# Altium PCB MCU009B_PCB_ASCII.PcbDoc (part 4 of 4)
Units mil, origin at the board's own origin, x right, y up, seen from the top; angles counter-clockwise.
Board outline 2657.23 x 2215.46 mil, 10 copper layers (Top Layer, Internal-Plane 2, Mid-Layer 3, Mid-Layer 4, Internal-Plane 5, Internal-Plane 6, Mid-Layer 7, Mid-Layer 8, Internal-Plane 9, Bottom Layer), stack 60.8 mil thick; 232 components, 196 nets, 851 pads, 493 vias.
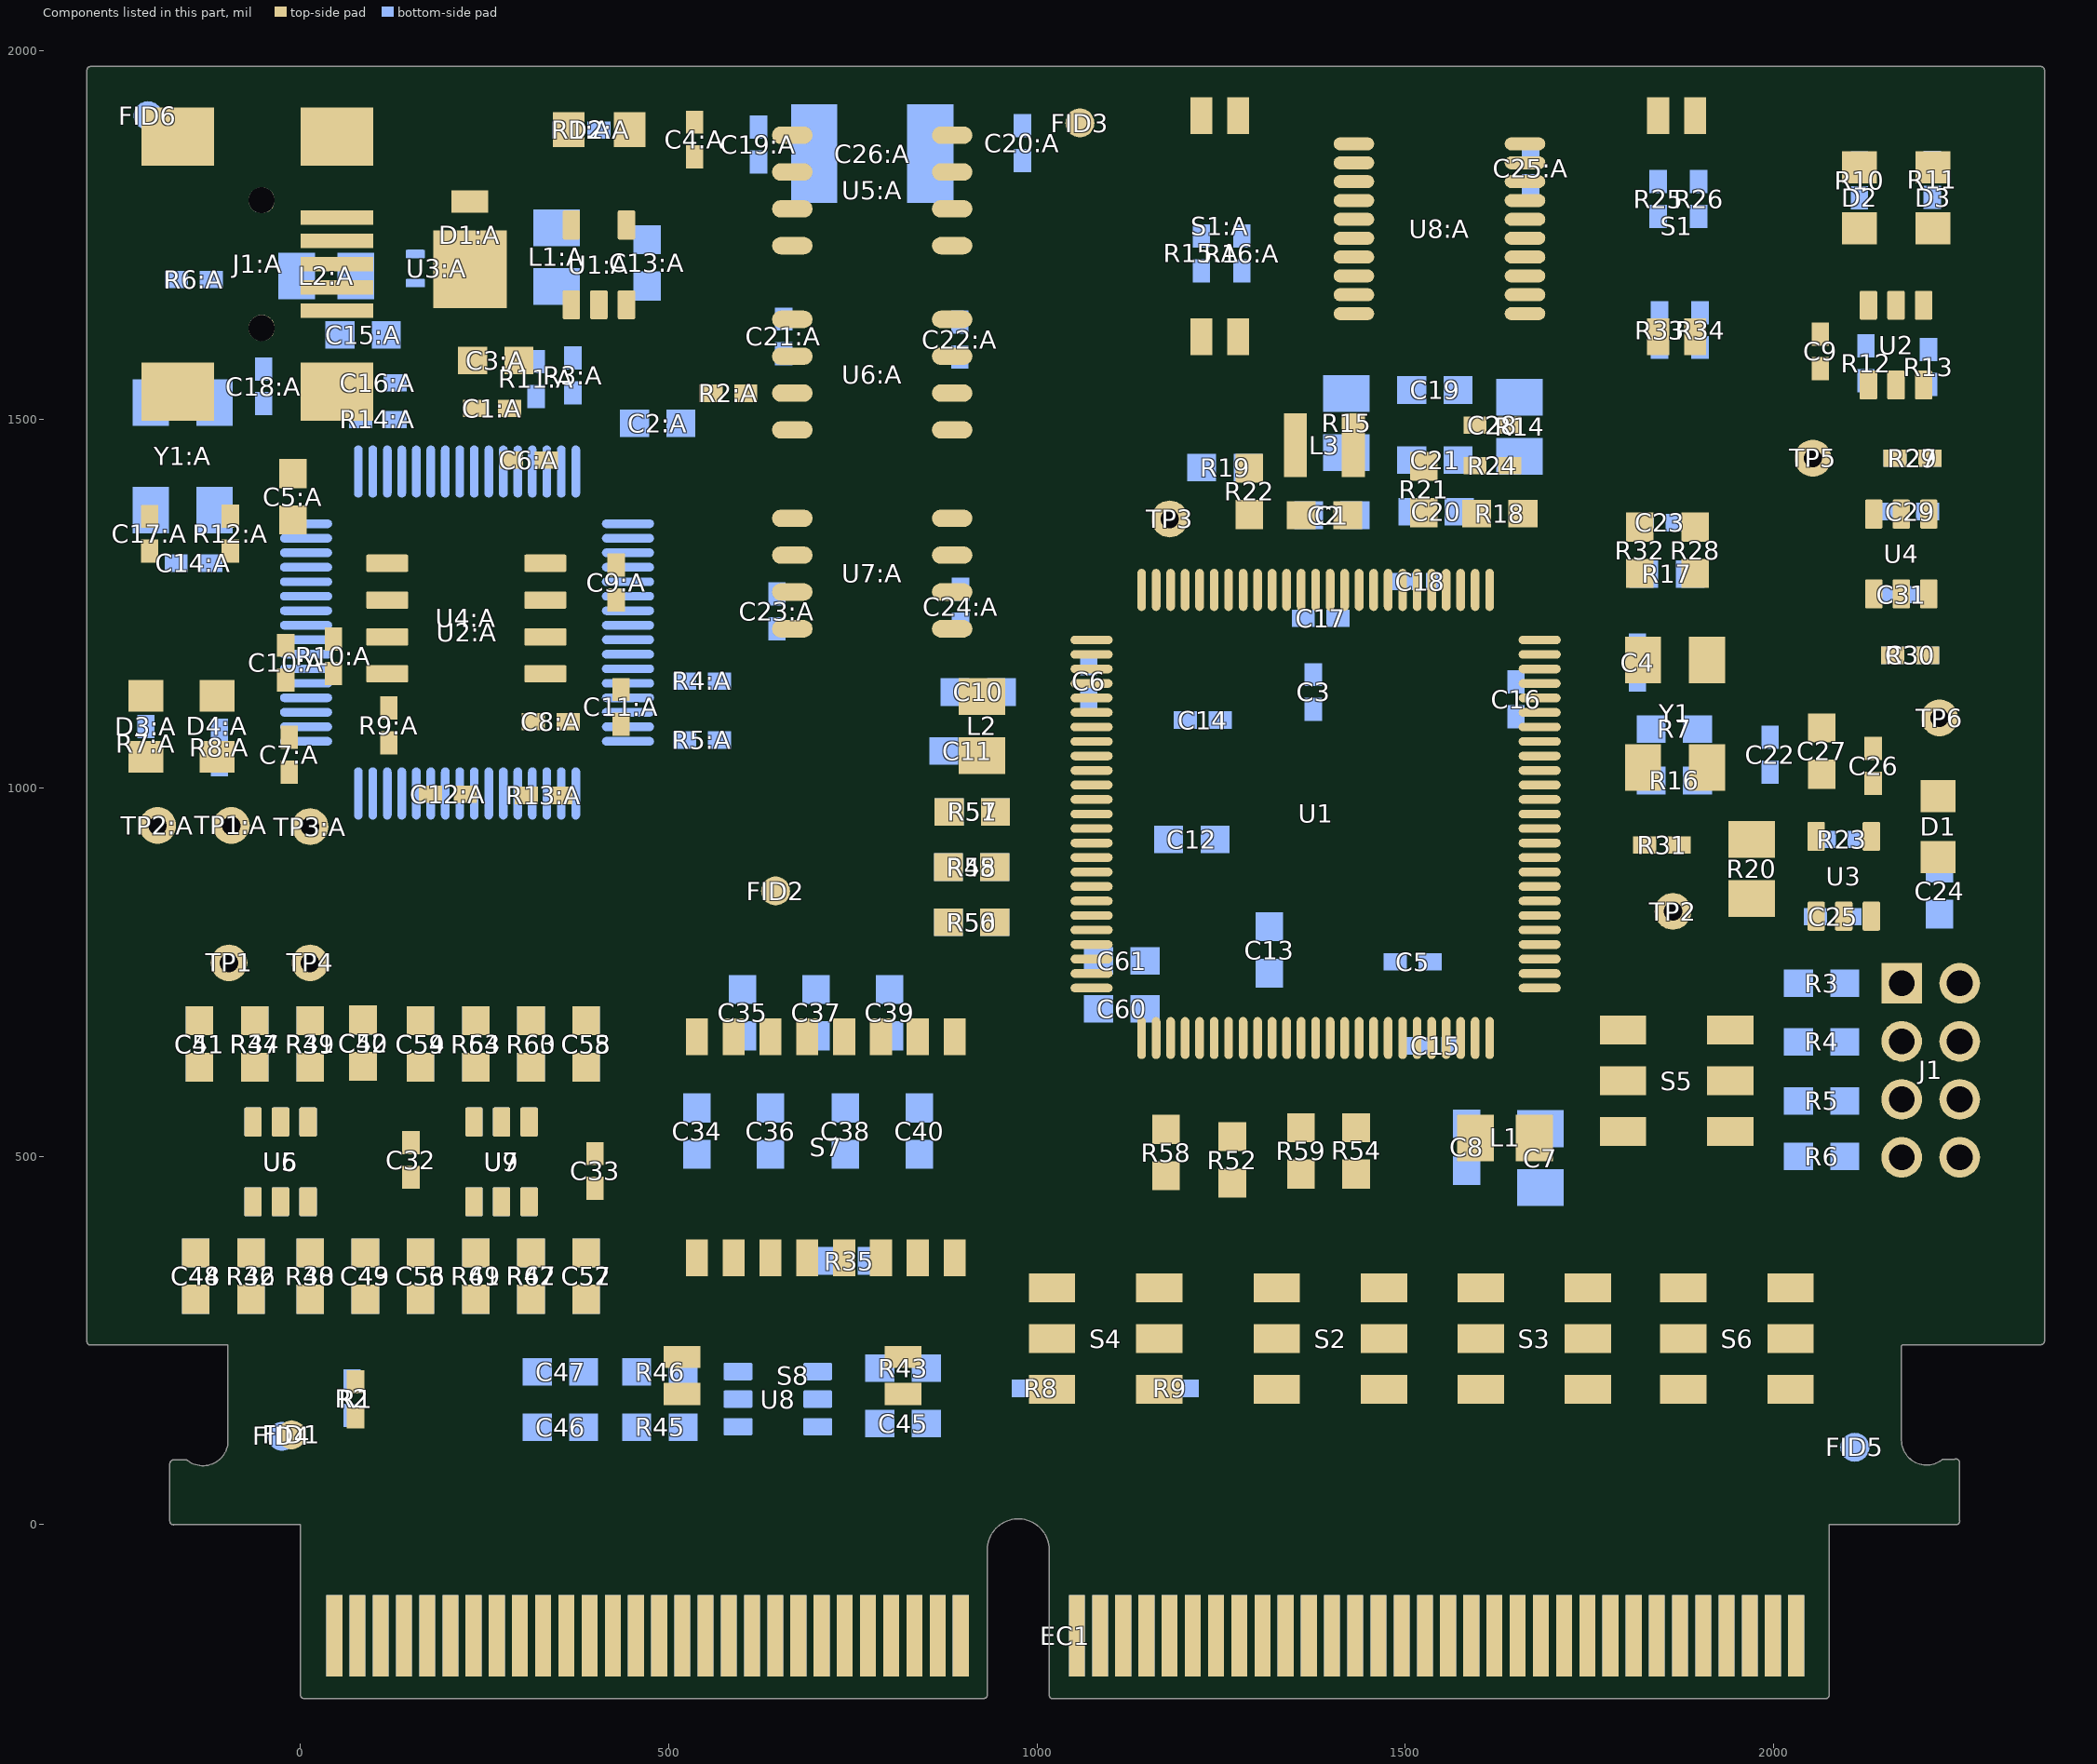
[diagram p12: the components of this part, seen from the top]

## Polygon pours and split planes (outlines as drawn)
GND on Mid-Layer 7 "Mid-Layer 7-No Net" (solid, pour order 6): -270,799 -270,264 -257,264 -99,264 cw(c-99,243) -78,243 -78,238 -78,113 cw(c-131,113) -131,60 -132,60 -136,60 -157,66 -157,20 -143,20 0,20 cw(c0,0) 20,0 20,-216 912,-216 912,-34 cw(c974,-34) 974,28 975,28 978,28 cw(c978,-31) 1037,-31 1037,-216 2055,-216 2055,-1 cw(c2076,-1) 2076,20 2232,20 2232,66 2218,61 2207,61 2204,61 cw(c2204,106.87) 2171.57,74.43 2164,82 cw(c2190.56,108.56) 2153,108.56 2153,122 2153,241 2153,242 cw(c2175,242) 2175,264 2347,264 2347,1959 2323,1959 827,1959 827,1123 827,1119 825,1117 793,1085 813,1085 985,1085 985,1127 985,1129 985,1128 1000,1141 1126,1141 1162,1105 1192,1105 1214,1083 1214,959 1232,941 1343,941 1365,919 1365,822 1402,785 1442,785 1510,717 1510,470 1432,392 995,392 946,343 946,220 781,55 777,55 774,58 774,62 936,224 936,347 991,402 1428,402 1500,474 1500,713 1438,775 1397,775 1355,818 1355,915 1339,931 1228,931 1204,955 1204,1079 1188,1095 1158,1095 1122,1131 1004,1131 995,1123 995,1075 990,1075 783,1075 507,799
EMU_GND on Internal-Plane 2 (split plane): 726,1160.07 464.77,898.84 -269.63,898.84 -269.63,1959.01 726,1959.01
GND on Internal-Plane 2 (split plane): 257 vertices, not listed, extent -269.63,-216.18 2347.33,1959.01
EMU_GND on Internal-Plane 5 (split plane): 725.99,1160.06 464.77,898.84 -269.63,898.84 -269.63,1959.01 725.99,1959.01
GND on Internal-Plane 5 (split plane): 235 vertices, not listed, extent -269.63,-216.18 2347.33,1959.01
MCU_1V2 on Internal-Plane 6 (split plane): 1706.9,1295.72 1706.9,1271 1707.29,1269.05 1708.4,1267.4 1764.9,1210.89 1764.9,1199.23 1764.9,1188 1765.29,1186.05 1766.4,1184.4 1768.05,1183.29 1769.86,1182.93 1779.4,1173.4 1781.05,1172.29 1781.61,1172.18 1804.9,1148.89 1804.9,1097.11 1748.89,1041.1 1735,1041.1 1733.05,1040.71 1731.4,1039.6 1686.4,994.6 1685.29,992.95 1684.9,991 1684.9,814.11 1661.4,790.6 1660.29,788.95 1659.9,787 1659.9,782 1659.9,695.1 1587.11,695.1 1555.1,727.11 1555.1,740 1555.1,765 1554.71,766.95 1553.6,768.6 1525.1,797.11 1525.1,870 1524.71,871.95 1523.6,873.6 1438.6,958.6 1436.95,959.71 1435,960.1 1432.11,960.1 1370.1,1022.11 1370.1,1157.89 1392.11,1179.9 1417.89,1179.9 1459.9,1137.89 1459.9,1122 1460.29,1120.05 1461.4,1118.4 1508.4,1071.4 1510.05,1070.29 1512,1069.9 1615,1069.9 1616.95,1070.29 1618.6,1071.4 1635.6,1088.4 1636.71,1090.05 1637.1,1092 1637.1,1138 1636.71,1139.95 1635.6,1141.6 1532.6,1244.6 1530.95,1245.71 1530.39,1245.82 1503.6,1272.6 1501.95,1273.71 1500,1274.1 1350,1274.1 1348.05,1273.71 1346.4,1272.6 1328.89,1255.1 1215,1255.1 1213.05,1254.71 1211.4,1253.6 1162.89,1205.1 1120,1205.1 1118.05,1204.71 1116.4,1203.6 1106.4,1193.6 1105.29,1191.95 1104.9,1190 1104.9,1141.1 995.1,1141.1 995.1,1231.16 995.1,1364.66 1045.34,1414.9 1587.72,1414.9
EMU_1V8 on Internal-Plane 6 (split plane): 329.38,1432.46 329.38,1369.12 314.09,1353.83 294.07,1353.83 279.57,1368.33 279.57,1386.09 279.18,1388.04 278.08,1389.69 276.42,1390.8 274.63,1391.15 266.95,1398.83 265.3,1399.94 263.35,1400.32 150.09,1400.32 148.14,1399.94 146.48,1398.83 136.15,1388.5 135.05,1386.84 134.66,1384.89 134.66,1153.21 135.05,1151.26 136.15,1149.61 172.31,1113.44 173.97,1112.34 175.92,1111.95 312.1,1111.95 365.15,1058.91 365.15,1030.94 336.34,1002.13 270.23,1002.13 239.43,1032.93 239.43,1068.57 239.05,1070.52 237.94,1072.17 215.69,1094.43 214.03,1095.53 212.08,1095.92 177.72,1095.92 175.77,1095.53 174.11,1094.43 119.18,1039.49 43.31,1039.49 7.36,1075.45 7.36,1290.31 6.97,1292.26 5.86,1293.92 -14.01,1313.79 -15.66,1314.89 -17.61,1315.28 -46.5,1315.28 -83.25,1352.03 -83.25,1388.74 -76.3,1395.69 -34.7,1395.69 -32.75,1396.08 -31.1,1397.18 13.51,1441.79 320.05,1441.79
MCU_3V3 on Internal-Plane 6 (split plane): 1524.4,1237.4 1526.05,1236.29 1526.61,1236.18 1626.9,1135.89 1626.9,1094.11 1612.89,1080.1 1514.11,1080.1 1470.1,1124.11 1470.1,1140 1469.71,1141.95 1468.6,1143.6 1423.6,1188.6 1421.95,1189.71 1420,1190.1 1390,1190.1 1388.05,1189.71 1386.4,1188.6 1361.4,1163.6 1360.29,1161.95 1359.9,1160 1359.9,1020 1360.29,1018.05 1361.4,1016.4 1426.4,951.4 1428.05,950.29 1430,949.9 1432.89,949.9 1514.9,867.89 1514.9,795 1515.29,793.05 1516.4,791.4 1544.9,762.89 1544.9,740 1544.9,725 1545.29,723.05 1546.4,721.4 1579.9,687.89 1579.9,665 1579.9,645 1579.9,635 1580.29,633.05 1581.4,631.4 1604.9,607.89 1604.9,580 1604.9,520.1 1510.1,520.1 1510.1,715 1509.71,716.95 1508.6,718.6 1443.6,783.6 1441.95,784.71 1440,785.1 1402.11,785.1 1365.1,822.11 1365.1,917 1364.71,918.95 1363.6,920.6 1344.6,939.6 1342.95,940.71 1341,941.1 1232.11,941.1 1214.1,959.11 1214.1,1081 1213.71,1082.95 1212.6,1084.6 1193.6,1103.6 1191.95,1104.71 1190,1105.1 1162.11,1105.1 1129.6,1137.6 1127.6,1139.6 1125.95,1140.71 1124,1141.1 1115.1,1141.1 1115.1,1187.89 1122.11,1194.9 1165,1194.9 1166.95,1195.29 1168.6,1196.4 1217.11,1244.9 1331,1244.9 1332.95,1245.29 1334.6,1246.4 1352.11,1263.9 1497.89,1263.9
MCU_A_3V3 on Internal-Plane 6 (split plane): 1122.4,1130.4 1156.4,1096.4 1158.05,1095.29 1160,1094.9 1187.89,1094.9 1203.9,1078.89 1203.9,957 1204.29,955.05 1205.4,953.4 1226.4,932.4 1228.05,931.29 1230,930.9 1338.89,930.9 1354.9,914.89 1354.9,820 1355.29,818.05 1356.4,816.4 1396.4,776.4 1398.05,775.29 1400,774.9 1437.89,774.9 1499.9,712.89 1499.9,227.11 1467.89,195.1 910,195.1 908.05,194.71 906.4,193.6 617.89,-94.9 238.11,-94.9 166.1,-22.89 166.1,309 165.71,310.95 164.6,312.6 93.6,383.6 91.95,384.71 90,385.1 -32.89,385.1 -49.9,402.11 -49.9,512.89 -27.89,534.9 0,534.9 1.95,535.29 3.6,536.4 13.6,546.4 14.71,548.05 15.1,550 15.1,667.89 92.11,744.9 540,744.9 541.95,745.29 543.6,746.4 872.11,1074.9 990,1074.9 991.95,1075.29 993.6,1076.4 994.71,1078.05 995.1,1080 995.1,1128.98 995.9,1130.9 1121.89,1130.9
3V3 on Internal-Plane 6 (split plane): 2347.33,895.1 2147.11,895.1 2128.6,913.6 2126.95,914.71 2125,915.1 2060,915.1 2058.05,914.71 2056.4,913.6 2016.4,873.6 2015.29,871.95 2014.9,870 2014.9,790 2015.29,788.05 2016.4,786.4 2054.9,747.89 2054.9,640 2054.9,202.11 1957.89,105.1 832.31,105.1 912.11,184.9 1470,184.9 1471.95,185.29 1473.6,186.4 1508.6,221.4 1509.71,223.05 1510.1,225 1510.1,509.9 1610,509.9 1611.95,510.29 1613.6,511.4 1614.71,513.05 1615.1,515 1615.1,580 1615.1,610 1614.71,611.95 1613.6,613.6 1590.1,637.11 1590.1,645 1590.1,684.9 1665,684.9 1666.95,685.29 1668.6,686.4 1669.71,688.05 1670.1,690 1670.1,782 1670.1,784.89 1693.6,808.4 1694.71,810.05 1695.1,812 1695.1,988.89 1737.11,1030.9 1751,1030.9 1752.95,1031.29 1754.6,1032.4 1813.6,1091.4 1814.71,1093.05 1815.1,1095 1815.1,1151 1814.71,1152.95 1813.6,1154.6 1787.6,1180.6 1785.95,1181.71 1785.39,1181.82 1775.6,1191.6 1775.1,1191.94 1775.1,1199.23 1775.1,1213 1774.71,1214.95 1773.6,1216.6 1717.1,1273.11 1717.1,1297.83 1716.71,1299.78 1715.6,1301.44 1593.44,1423.6 1591.78,1424.71 1589.83,1425.1 1043.23,1425.1 1041.27,1424.71 1039.62,1423.6 986.4,1370.38 985.29,1368.73 984.9,1366.77 984.9,1231.16 984.9,1130 984.9,1085.1 870,1085.1 868.05,1084.71 866.4,1083.6 537.89,755.1 90,755.1 88.05,754.71 86.4,753.6 6.4,673.6 5.29,671.95 4.9,670 4.9,552.11 -2.11,545.1 -30,545.1 -31.95,544.71 -33.6,543.6 -58.6,518.6 -59.71,516.95 -60.1,515 -60.1,400 -59.71,398.05 -58.6,396.4 -38.6,376.4 -36.95,375.29 -35,374.9 87.89,374.9 155.9,306.89 155.9,205.1 67.11,205.1 -61.4,333.6 -63.05,334.71 -65,335.1 -97.89,335.1 -149.9,387.11 -149.9,593.11 -121.26,626.53 -26.4,721.4 -25.29,723.05 -24.9,725 -24.9,798.84 506.2,798.84 825.99,1118.64 825.99,1959.01 2347.33,1959.01
EMU_3V3 on Internal-Plane 6 (split plane): 725.99,1160.06 464.77,898.84 -269.63,898.84 -269.63,1959.01 725.99,1959.01
HSEC_5V0 on Internal-Plane 6 (split plane): 187 vertices, not listed, extent -269.63,-216.18 2347.33,904.9
EMU_GND on Internal-Plane 9 (split plane): 726.08,1160.16 464.87,898.94 -269.63,898.94 -269.63,1959.01 726.08,1959.01
GND on Internal-Plane 9 (split plane): 233 vertices, not listed, extent -269.63,-216.18 2347.33,1959.01

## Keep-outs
Keep-Out Layer:
  text ".Layer_Name" at -3604.9,-2856.09 h60

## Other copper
Top Layer:
  text ".Layer_Name" at -3604.9,-2856.09 h60
Mid-Layer 3:
  text ".Layer_Name" at -3619,-2847 h60
Mid-Layer 4:
  text ".Layer_Name" at -3600,-2847 h60
Mid-Layer 7:
  text ".Layer_Name" at -3595,-2852 h60
Mid-Layer 8:
  text ".Layer_Name" at -3600,-2846 h60
Bottom Layer:
  text ".Layer_Name" at -3604.9,-2856.09 h60
Internal-Plane 2 (plane layer: these items are gaps in the copper):
  rectangle: -293.8,798.84 506.2,898.84
  rectangle: 726,1119 826,1977
  region: 506.19,798.84 825.99,1118.64 755.28,1189.35 435.48,869.55
  lines w10: 697.45,1007.09 697.45,1017.86 ; 776,1080 990,1080 990,1092.75 990,1118.25 990,1119.44 990,1125.81 1002.16,1136 1040,1136 1124,1136 1160,1100 1190,1100 1209,1081 1209,957 1230,936 1341,936 1360,917 1360,820 1400,780 1420,780 1440,780 1505,715 1505,472 1430,397 993,397 941,345 941,222 799,80 779,60 ; 776.47,1115.01 783.39,1121.93
  lines w40: -289.73,248.71 ccw(c-284.72,248.71) -284.72,243.7 -98.73,243.7 -98.73,238.74 ccw(c-93.71,238.74) -98.32,236.75 -98.32,115.84 -98.31,115.56 cw(c-132.26,113.93) -98.27,113.93 cw(c-132.26,113.93) -152.76,86.83 ccw(c-155.78,82.83) -155.78,87.84 -172.11,87.84 ccw(c-172.11,82.83) -175.66,86.37 -175.72,86.31 ccw(c-172.18,82.76) -177.19,82.76 -177.19,4.84 ccw(c-172.18,4.84) -171.01,-0.04 0.06,-0.04 0.06,-231.05 ccw(c5.07,-231.05) 5.9,-236 927.51,-236 ccw(c927.51,-230.98) 932.53,-230.98 ccw(c927.51,-230.98) 932.32,-229.56 932.32,-35.08 932.42,-34.1 cw(c974.4,-34.1) 1016.39,-34.1 1016.39,-231.27 ccw(c1021.4,-231.27) 1017.85,-234.81 1017.92,-234.88 ccw(c1021.47,-231.33) 1021.47,-236.35 1034.75,-236.35 1035.58,-236.28 2070.22,-236.28 ccw(c2070.22,-231.26) 2075.23,-231.26 2075.16,-230.44 2075.16,-0.11 2247.39,-0.11 ccw(c2247.39,4.91) 2252.41,4.91 ccw(c2247.39,4.91) 2252.2,6.33 2252.2,84.13 ccw(c2247.19,84.13) 2245.21,88.74 2230.93,88.74 ccw(c2230.93,83.73) 2227.9,87.73 cw(c2207.4,114.83) 2173.42,114.71 2173.42,242.73 2174.88,244.19 2362.35,244.19 ccw(c2362.35,249.21) 2365.9,245.66 2365.96,245.72 ccw(c2362.41,249.27) 2367.42,249.27 2367.42,1973.27 2367.49,1974.1 ccw(c2362.48,1974.1) 2362.48,1979.11 -284.69,1979.11 ccw(c-284.69,1974.1) -288.23,1977.64 -288.26,1977.62 ccw(c-284.72,1974.07) -289.73,1974.07 -289.73,248.71
  text ".Layer_Name" at -3619,-2838 h60
Internal-Plane 9 (plane layer: these items are gaps in the copper):
  region: 506.29,798.94 826.08,1118.73 755.37,1189.44 435.58,869.65
  rectangle: -293.71,798.94 506.29,898.94
  rectangle: 726.08,1118.73 826.08,1976.73
  lines w10: 760,1080 975,1080 990,1080 990,1125 1001,1136 1074,1136 1124,1136 1160,1100 1190,1100 1209,1081 1209,957 1230,936 1341,936 1360,917 1360,820 1400,780 1440,780 1505,715 1505,472 1430,397 993,397 941,345 941,222 779,60
  lines w40: -289.73,248.71 ccw(c-284.72,248.71) -284.72,243.7 -98.73,243.7 -98.73,238.74 ccw(c-93.71,238.74) -98.32,236.75 -98.32,115.84 -98.31,115.56 cw(c-132.26,113.93) -98.27,113.93 cw(c-132.26,113.93) -152.76,86.83 ccw(c-155.78,82.83) -155.78,87.84 -172.11,87.84 ccw(c-172.11,82.83) -175.66,86.37 -175.72,86.31 ccw(c-172.18,82.76) -177.19,82.76 -177.19,4.84 ccw(c-172.18,4.84) -171.01,-0.04 0.06,-0.04 0.06,-231.05 ccw(c5.07,-231.05) 5.9,-236 927.51,-236 ccw(c927.51,-230.98) 932.53,-230.98 ccw(c927.51,-230.98) 932.32,-229.56 932.32,-35.08 932.42,-34.1 cw(c974.4,-34.1) 1016.39,-34.1 1016.39,-231.27 ccw(c1021.4,-231.27) 1017.85,-234.81 1017.92,-234.88 ccw(c1021.47,-231.33) 1021.47,-236.35 1034.75,-236.35 1035.58,-236.28 2070.22,-236.28 ccw(c2070.22,-231.26) 2075.23,-231.26 2075.16,-230.44 2075.16,-0.11 2247.39,-0.11 ccw(c2247.39,4.91) 2252.41,4.91 ccw(c2247.39,4.91) 2252.2,6.33 2252.2,84.13 ccw(c2247.19,84.13) 2245.21,88.74 2230.93,88.74 ccw(c2230.93,83.73) 2227.9,87.73 cw(c2207.4,114.83) 2173.42,114.71 2173.42,242.73 2174.88,244.19 2362.35,244.19 ccw(c2362.35,249.21) 2365.9,245.66 2365.96,245.72 ccw(c2362.41,249.27) 2367.42,249.27 2367.42,1973.27 2367.49,1974.1 ccw(c2362.48,1974.1) 2362.48,1979.11 -284.69,1979.11 ccw(c-284.69,1974.1) -288.23,1977.64 -288.26,1977.62 ccw(c-284.72,1974.07) -289.73,1974.07 -289.73,248.71
  text ".Layer_Name" at -3603,-2855 h60
Internal-Plane 6 (plane layer: these items are gaps in the copper):
  rectangle: 725.99,1118.64 825.99,1976.64
  region: 506.19,798.84 825.99,1118.64 755.28,1189.35 435.48,869.55
  rectangle: -293.8,798.84 506.2,898.84
  lines w10: -30,800 -30,725 -125,630 -155,595 -155,385 -100,330 -91.25,330 -73.75,330 -65,330 65,200 160,200 ; 820,100 1960,100 2060,200 2060,640 2060,750 2020,790 2020,870 2060,910 2125,910 2145,890 2370,890 ; 1110,1136 1110,1190 1120,1200 1165,1200 1215,1250 1331,1250 1350,1269 1500,1269 1528,1241 1529,1241 1632,1138 1632,1092 1615,1075 1512,1075 1465,1122 1465,1140 1420,1185 1390,1185 1365,1160 1365,1020 1430,955 1435,955 1520,870 1520,795 1550,765 1550,740 1550,725 1585,690 ; 1505,515 1610,515 1610,580 1610,610 1585,635 ; 1585,645 1585,635 ; 1585,665 1585,690 ; 990,1130 990,1231.16 990,1366.77 1043.23,1420 1589.83,1420 1712,1297.83 1712,1271 1770,1213 1770,1199.23 1770,1188 1772,1188 1783,1177 1784,1177 1810,1151 1810,1095 1751,1036 1735,1036 1690,991 1690,812 1665,787 1665,782 1665,690 1585,690 ; 990,1130 990,1080 900,1080 870,1080 540,750 90,750 10,670 10,550 0,540 -30,540 -55,515 -55,400 -35,380 -10,380 90,380 161,309 161,-25 236,-100 620,-100 910,190 1470,190 1505,225 1505,715 1440,780 1400,780 1360,820 1360,917 1341,936 1230,936 1209,957 1209,1081 1190,1100 1160,1100 1126,1134 1124,1136 1027.5,1136 992.5,1136 990,1130 ; 1585,635 1585,690 ; -88.35,1349.92 -88.35,1390.85 -78.41,1400.79 -34.7,1400.79 11.4,1446.89 322.16,1446.89 334.48,1434.57 334.48,1367.01 316.2,1348.73 291.96,1348.73 274.47,1366.22 274.47,1386.09 272.49,1386.09 263.35,1395.23 150.09,1395.23 139.76,1384.89 139.76,1153.21 175.92,1117.05 314.21,1117.05 370.24,1061.02 370.24,1028.83 338.45,997.04 268.11,997.04 234.34,1030.81 234.34,1068.57 212.08,1090.82 177.72,1090.82 121.29,1034.39 41.2,1034.39 2.26,1073.34 2.26,1290.31 -17.61,1310.18 -48.61,1310.18 -88.35,1349.92
  lines w40: -289.73,248.71 ccw(c-284.72,248.71) -284.72,243.7 -98.73,243.7 -98.73,238.74 ccw(c-93.71,238.74) -98.32,236.75 -98.32,115.84 -98.31,115.56 cw(c-132.26,113.93) -98.27,113.93 cw(c-132.26,113.93) -152.76,86.83 ccw(c-155.78,82.83) -155.78,87.84 -172.11,87.84 ccw(c-172.11,82.83) -175.66,86.37 -175.72,86.31 ccw(c-172.18,82.76) -177.19,82.76 -177.19,4.84 ccw(c-172.18,4.84) -171.01,-0.04 0.06,-0.04 0.06,-231.05 ccw(c5.07,-231.05) 5.9,-236 927.51,-236 ccw(c927.51,-230.98) 932.53,-230.98 ccw(c927.51,-230.98) 932.32,-229.56 932.32,-35.08 932.42,-34.1 cw(c974.4,-34.1) 1016.39,-34.1 1016.39,-231.27 ccw(c1021.4,-231.27) 1017.85,-234.81 1017.92,-234.88 ccw(c1021.47,-231.33) 1021.47,-236.35 1034.75,-236.35 1035.58,-236.28 2070.22,-236.28 ccw(c2070.22,-231.26) 2075.23,-231.26 2075.16,-230.44 2075.16,-0.11 2247.39,-0.11 ccw(c2247.39,4.91) 2252.41,4.91 ccw(c2247.39,4.91) 2252.2,6.33 2252.2,84.13 ccw(c2247.19,84.13) 2245.21,88.74 2230.93,88.74 ccw(c2230.93,83.73) 2227.9,87.73 cw(c2207.4,114.83) 2173.42,114.71 2173.42,242.73 2174.88,244.19 2362.35,244.19 ccw(c2362.35,249.21) 2365.9,245.66 2365.96,245.72 ccw(c2362.41,249.27) 2367.42,249.27 2367.42,1973.27 2367.49,1974.1 ccw(c2362.48,1974.1) 2362.48,1979.11 -284.69,1979.11 ccw(c-284.69,1974.1) -288.23,1977.64 -288.26,1977.62 ccw(c-284.72,1974.07) -289.73,1974.07 -289.73,248.71
  text ".Layer_Name" at -3581,-2857 h60
Internal-Plane 5 (plane layer: these items are gaps in the copper):
  rectangle: 725.99,1118.64 825.99,1976.64
  region: 506.19,798.84 825.99,1118.64 755.28,1189.35 435.48,869.55
  rectangle: -293.8,798.84 506.2,898.84
  lines w10: 727,1080 990,1080 990,1126 1000,1136 1124,1136 1160,1100 1190,1100 1209,1081 1209,957 1230,936 1341,936 1360,917 1360,820 1400,780 1440,780 1505,715 1505,472 1430,397 1023,397 993,397 941,345 941,222 779,60
  lines w40: -289.73,248.71 ccw(c-284.72,248.71) -284.72,243.7 -98.73,243.7 -98.73,238.74 ccw(c-93.71,238.74) -98.32,236.75 -98.32,115.84 -98.31,115.56 cw(c-132.26,113.93) -98.27,113.93 cw(c-132.26,113.93) -152.76,86.83 ccw(c-155.78,82.83) -155.78,87.84 -172.11,87.84 ccw(c-172.11,82.83) -175.66,86.37 -175.72,86.31 ccw(c-172.18,82.76) -177.19,82.76 -177.19,4.84 ccw(c-172.18,4.84) -171.01,-0.04 0.06,-0.04 0.06,-231.05 ccw(c5.07,-231.05) 5.9,-236 927.51,-236 ccw(c927.51,-230.98) 932.53,-230.98 ccw(c927.51,-230.98) 932.32,-229.56 932.32,-35.08 932.42,-34.1 cw(c974.4,-34.1) 1016.39,-34.1 1016.39,-231.27 ccw(c1021.4,-231.27) 1017.85,-234.81 1017.92,-234.88 ccw(c1021.47,-231.33) 1021.47,-236.35 1034.75,-236.35 1035.58,-236.28 2070.22,-236.28 ccw(c2070.22,-231.26) 2075.23,-231.26 2075.16,-230.44 2075.16,-0.11 2247.39,-0.11 ccw(c2247.39,4.91) 2252.41,4.91 ccw(c2247.39,4.91) 2252.2,6.33 2252.2,84.13 ccw(c2247.19,84.13) 2245.21,88.74 2230.93,88.74 ccw(c2230.93,83.73) 2227.9,87.73 cw(c2207.4,114.83) 2173.42,114.71 2173.42,242.73 2174.88,244.19 2362.35,244.19 ccw(c2362.35,249.21) 2365.9,245.66 2365.96,245.72 ccw(c2362.41,249.27) 2367.42,249.27 2367.42,1973.27 2367.49,1974.1 ccw(c2362.48,1974.1) 2362.48,1979.11 -284.69,1979.11 ccw(c-284.69,1974.1) -288.23,1977.64 -288.26,1977.62 ccw(c-284.72,1974.07) -289.73,1974.07 -289.73,248.71
  text ".Layer_Name" at -3576,-2852 h60

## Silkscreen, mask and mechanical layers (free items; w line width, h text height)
Top Overlay:
  region: 2292.34,1969.69 2292.34,1825 2357,1825 2357,1969.69
  lines w4: -45,255 -25,275
  text "ON" at 1140.99,1898 h20
  text "1" at 1946,1898 h20
  text "-" at 2344,1763 h40 r90
  text "BOOT" at 1983,1724 h20 r90
  text ".PCB_Rev" at 2342,1691 h40 r90
  text "JTAG ISO" at 1152,1683 h20 r90
  text "UART ISO" at 1363,1683 h20 r90
  text "OFF" at 1121,1602 h20
  text "0" at 1941,1601 h20
  text "OutFilt" at 818,703 h20
  text "C2000 F28004x controlCARD" at 2346,665 h40 r90
  text "PGA" at 979,486 h20 r90
  text "cJTAG" at 1049,388 h20
  text "Thru" at 861.32,297 h20
  text "Int" at 479,119 h20
  text "Ext" at 809,119 h20
  text "VREFHI" at 576,93 h20
  text "Std JTAG" at 1025,75 h20
  text "1" at 46.06,6.81 h30
  text "57" at 1038.19,6.81 h30
  text "119" at 1955.51,6.81 h30
  text "55" at 870,-5 h30
  text ".Layer_Name" at -3604.9,-2856.09 h60
Bottom Overlay:
  text "TMDSCNCD280049C" at 1892,111 h40
  text "'.PCB_Rev'" at 1648,48 h40
  text ".PRJ_Number" at 1891,48 h40
  text "2" at 57.87,6.81 h30
  text "58" at 1089.37,6.81 h30
  text "120" at 2022.44,6.81 h30
  text "56" at 915,-5 h30
  text ".Layer_Name" at -3604.9,-2856.09 h60
Top Paste:
  text ".Layer_Name" at -3604.9,-2856.09 h60
Bottom Paste:
  text ".Layer_Name" at -3604.9,-2856.09 h60
Top Solder:
  text ".Layer_Name" at -3604.9,-2856.09 h60
  text ".Layer_Name" at -3604.9,-2856.09 h60
Bottom Solder:
  text ".Layer_Name" at -3604.9,-2856.09 h60
Drill Guide:
  text ".Layer_Name" at -3604.9,-2856.09 h60
M1 Board Outline:
  lines w4: -284.78,1474.65 -284.78,248.72 -284.76,248.7 -93.62,248.7 -93.75,248.57 -93.75,115.24 -93.68,115.18 ; -284.78,1947.09 -284.68,1947.19 -284.68,1973.99 -284.57,1974.1 2362.36,1974.1 2362.36,249.2 2168.79,249.2 2168.46,248.86 2168.46,116.77 ccw(c2207.41,114.86) 2230.94,83.76 2247.19,83.76 2247.24,83.8 2247.24,4.91 ; -93.34,115.83 cw(c-132.3,113.92) -155.82,82.82 -172.1,82.82 -172.14,82.78 -172.14,4.89 -172.08,4.95 5.05,4.95 5.11,4.89 5.11,-231.04 5.17,-230.98 927.3,-230.98 927.3,-34.43 ; 1022.44,-34.43 1022.44,-231.33 1022.51,-231.27 2070.19,-231.27 2070.19,4.83 2070.27,4.91 2247.24,4.91 ; 2247.24,4.91 2247.24,4.91
  text ".Layer_Name" at -3593,-2846 h60
M2 Board Dimensions:
  rectangle: -4056.9,-2397.6 -3681.9,-2272.6
  rectangle: -4181.9,-2272.6 -4056.9,-2147.6
  lines w7: -4181.9,-2272.6 -3181.9,-2272.6 ; -4056.9,-2397.6 -4056.9,-2147.6 ; -3931.9,-2397.6 -3931.9,-2147.6 ; -3681.9,-2397.6 -3681.9,-2147.6 ; -3431.9,-2397.6 -3431.9,-2147.6 ; -4181.9,-2397.6 -4181.9,-2147.6 -3181.9,-2147.6 -3181.9,-2397.6 -4181.9,-2397.6
  lines w10: -3200,-522 -3132,-522 ; -3158,-551 -3131,-523 ; -3158,-492 -3131,-522 ; -3124,823 -3056,905 ; -3122,-569 -3122,-247 ; -3122,-206 -3072,-260 -2962,-260 -2915,-203 ; -3122,-204 -3122,826 ; -3057,906 -2993,819 ; -3039,-354 -2971,-354 ; -2997,-383 -2970,-355 ; -2997,-324 -2970,-354 ; -2992,818 -2920,908 ; -2961,-569 -2961,-287 ; -2915,-204 -2915,826 -2915,911 ; -2914,-569 -2914,-247 ; -2908.04,446.62 cw(c-2964,-261) -2524.66,296.54 ; -2906.16,445.26 ccw(c-2766.4,679.92) -2855.29,421.66 ; -2906,-519 -2879,-549 ; -2906,-518 -2879,-490 ; -2906,452 cw(c-2873.55,278.02) -2843.28,452.39 ; -2904,-518 -2836,-518 ; -2904,-355 -2877,-385 ; -2904,-354 -2877,-326 ; -2902,-354 -2834,-354 ; -2888,-165 -2425,407 ; -2578,311 ccw(c-2440.48,651.43) -2523.34,293.74 ; -2560.75,344.3 cw(c-2677.61,210.86) -2522,296
  text "30" at -2719,467 h60
  text "18MIL" at -2793,-382 h60
  text "62MIL" at -2800,-546 h60
  text "GOLD FINGER" at -3281,-783 h60
  text "SIDE VIEW" at -3227,-896 h60
  text ".Layer_Name" at -3604.9,-2856.09 h60
M3 3D STEP Top:
  text ".Layer_Name" at -3604.9,-2856.09 h60
M4 3D STEP Bottom:
  text ".Layer_Name" at -3604.9,-2856.09 h60
M5 Assembly Top:
  lines w10: -4473.9,-2927.77 2126.1,-2927.77 ; -4473.9,-2724.43 2128.1,-2724.43 ; -4473.9,-2521.1 -4473.9,-3131.1 -468.9,-3131.1 2128.1,-3131.1 2128.1,-2521.1 -4473.4,-2521.1 -4473.4,-3131.1 -2897.9,-3131.1 ; -2008.9,-3131.1 -2008.9,-2521.1 ; -741.9,-2724.43 -741.9,-2521.1 ; 98.1,-2724.43 98.1,-2521.1 ; 720.1,-3137.6 720.1,-2934.77
  text "COMPONENTS MARKED 'DNP' SHOULD NOT BE POPULATED." at -3028.4,-2316.1 h60
  text "ASSEMBLY VARIANT:" at -3028.9,-2431.6 h60
  text ".VariantName" at -1992.9,-2431.6 h60
  text "PCB VIEWED FROM TOP SIDE" at -4410.4,-2653.27 h60
  text "BOARD #:" at -1933.9,-2653.27 h60
  text ".PRJ_Number" at -1388.4,-2653.27 h60
  text "REV:" at -543.9,-2653.27 h60
  text ".PCB_Rev" at -252.4,-2653.27 h60
  text "SVN REV:" at 294.1,-2653.27 h60
  text ".VersionControl_RevNumber" at 800.1,-2653.27 h60
  text "TID #:" at -1933.9,-2856.6 h60
  text ".TID" at -1388.4,-2856.6 h60
  text "PLOT NAME =" at -4410.4,-3061.94 h60
  text ".plot_File_Name" at -3604.9,-3061.94 h60
  text "GENERATED    :" at -1931.9,-3061.94 h60
  text ".Print_Date" at -1062.4,-3061.94 h60
  text ".Print_Time" at -333.4,-3061.94 h60
  text "TEXAS INSTRUMENTS" at 931.1,-3061.94 h60
M6 Assembly Bottom:
  lines w10: -4474.4,-2724.93 2127.6,-2724.93 ; -4472.4,-2928.27 2127.6,-2928.27 ; -3066.4,-3138.1 -3066.4,-2935.27 ; -2444.4,-2724.93 -2444.4,-2521.6 ; -1604.4,-2724.93 -1604.4,-2521.6 ; -337.4,-3131.6 -337.4,-2521.6 ; 551.6,-3131.6 2127.1,-3131.6 2127.1,-2521.6 -4474.4,-2521.6 -4474.4,-3131.6 -1877.4,-3131.6 2127.6,-3131.6 2127.6,-2521.6
  text "COMPONENTS MARKED 'DNP' SHOULD NOT BE POPULATED." at 1920.1,-2315.6 h60
  text ".VariantName" at 876.1,-2431.6 h60
  text "ASSEMBLY VARIANT:" at 1915.1,-2431.6 h60
  text ".VersionControl_RevNumber" at -3146.4,-2653.77 h60
  text "SVN REV:" at -2640.4,-2653.77 h60
  text ".PCB_Rev" at -2093.9,-2653.77 h60
  text "REV:" at -1802.4,-2653.77 h60
  text ".PRJ_Number" at -957.9,-2653.77 h60
  text "BOARD #:" at -412.4,-2653.77 h60
  text "PCB VIEWED FROM BOTTOM SIDE" at 2064.1,-2653.77 h60
  text ".TID" at -957.9,-2857.1 h60
  text "TID #:" at -412.4,-2857.1 h60
  text "TEXAS INSTRUMENTS" at -3277.4,-3062.44 h60
  text ".Print_Time" at -2012.9,-3062.44 h60
  text ".Print_Date" at -1283.9,-3062.44 h60
  text "GENERATED    :" at -414.4,-3062.44 h60
  text ".plot_File_Name" at 1258.6,-3062.44 h60
  text "PLOT NAME =" at 2064.1,-3062.44 h60
M9 Title Sheet:
  lines w10: -4673.4,-956.1 -4473.4,-956.1 ; -4673.4,1418.9 -4473.4,1418.9 ; -4673.4,3793.9 -4473.4,3793.9 ; -4473.4,-3133.1 -4473.4,5966.9 ; -4473.4,-3131.1 10126.6,-3131.1 ; -4473.4,5968.9 10126.6,5968.9 10126.6,-3131.1 ; -2173.4,-3331.1 -2173.4,-3131.1 ; -2173.4,5968.9 -2173.4,6168.9 ; 326.6,-3331.1 326.6,-3131.1 ; 326.6,5968.9 326.6,6168.9 ; 2139.1,-3131.1 2139.1,-2521.1 7121.6,-2521.1 ; 2826.6,-3331.1 2826.6,-3131.1 ; 2826.6,5968.9 2826.6,6168.9 ; 5326.6,-3331.1 5326.6,-3131.1 ; 5326.6,5968.9 5326.6,6168.9 ; 7121.6,-3131.1 7121.6,-2521.1 ; 7121.6,-2821.1 10121.6,-2821.1 ; 7121.6,-2221.1 10121.6,-2221.1 ; 7122.6,-1627.1 10122.6,-1627.1 ; 7826.6,-3331.1 7826.6,-3131.1 ; 7826.6,5968.9 7826.6,6168.9 ; 8626.6,-3121.1 8626.6,-2521.1 ; 10121.6,-2521.1 7121.6,-2521.1 ; 10121.6,-1921.1 7121.6,-1921.1 ; 10126.6,-1931.1 10126.6,-3131.1 ; 10126.6,-1126.6 7122.6,-1126.6 7121.6,-1126.6 7121.6,-1627.1 7121.6,-1921.1 ; 10126.6,-956.1 10326.6,-956.1 ; 10126.6,1418.9 10326.6,1418.9 ; 10126.6,3793.9 10326.6,3793.9 ; 7121.6,-2521.1 7121.6,-1921.1 ; -4673.4,-3331.1 10326.6,-3331.1 10326.6,6168.9 -4673.4,6168.9 -4673.4,-3331.1 ; -284.72,248.71 -93.71,248.71 -93.71,238.74 -93.3,238.33 -93.3,115.84 cw(c-132.26,113.93) -155.78,82.83 -172.11,82.83 -172.18,82.76 -172.18,69.68 -172.18,4.84 -172.04,4.98 4.59,4.98 5.07,4.5 5.07,-231.05 5.14,-230.98 20.63,-230.98 927.51,-230.98 927.3,-230.78 927.3,-34.2 927.4,-34.1 cw(c974.4,-34.1) 1021.4,-34.1 1021.4,-231.27 1021.47,-231.33 1034.75,-231.33 1034.82,-231.26 2070.22,-231.26 2070.15,-231.19 2070.15,4.77 2070.29,4.91 2247.39,4.91 2247.19,5.11 2247.19,84.13 2246.78,83.73 2230.93,83.73 cw(c2207.4,114.83) 2168.4,114.7 2168.4,244.8 2172.81,249.21 2362.35,249.21 2362.41,249.27 2362.41,1974.03 2362.48,1974.1 -284.69,1974.1 -284.72,1974.07 -284.72,248.71
  text "1" at -3442.06,6038.9 h70
  text "2" at -946.4,6038.9 h70
  text "3" at 1542.94,6038.9 h70
  text "4" at 4049.61,6038.9 h70
  text "5" at 6548.6,6038.9 h70
  text "6" at 9053.6,6038.9 h70
  text "A" at -4598.4,4895.9 h70
  text "A" at 10201.6,4895.9 h70
  text "B" at -4598.4,2515.9 h70
  text "B" at 10201.6,2515.9 h70
  text "C" at -4598.4,140.9 h70
  text "C" at 10201.6,140.9 h70
  text "PROJECT TITLE:" at 7161.6,-1720.1 h45
  text ".PRJ_Title" at 7211.6,-1853.43 h70
  text "DESIGNED FOR:" at 7161.6,-2021.1 h45
  text ".PRJ_Customer" at 7211.6,-2161.1 h70
  text "D" at -4598.4,-2229.1 h70
  text "D" at 10201.6,-2229.1 h70
  text "FILE NAME:" at 7161.6,-2321.1 h45
  text ".PCB_File_Name_No_Path" at 7211.6,-2441.1 h70
  text "Texas Instruments (TI) and/or its licensors do not warrant the accuracy or completeness of this specification" at 2192.1,-2602.94 h45
  text "ENGINEER:" at 7161.6,-2611.1 h45
  text "LAYOUT BY:" at 8666.6,-2611.1 h45
  text "or any information contained therein. TI and/or its licensors do not warrant that this design will meet" at 2147.11,-2715.6 h45
  text ".PRJ_Engineer" at 7211.6,-2766.09 h70
  text "QC Graphics Inc." at 8717.1,-2766.09 h70
  text "the specifications, will be suitable for your application or fit for any particular purpose, or will operate in" at 2147.11,-2828.27 h45
  text ".Layer_Name" at -3604.9,-2856.09 h60
  text "ALTIUM DESIGNER VERSION:" at 8666.6,-2921.1 h45
  text "an implementation. TI and/or its licensors do not warrant that the design is production worthy. You should" at 2147.11,-2940.93 h45
  text "completely validate and test your design implementation to confirm the system functionality for your application." at 2192.1,-3053.6 h45
  text ".print_Scale" at 7211.6,-3054.43 h70
  text ".Application_BuildNumber" at 8717.1,-3054.43 h70
  text "1" at -3442.06,-3261.1 h70
  text "2" at -946.4,-3261.1 h70
  text "3" at 1542.94,-3261.1 h70
  text "4" at 4049.61,-3261.1 h70
  text "5" at 6548.6,-3261.1 h70
  text "6" at 9053.6,-3261.1 h70
M10 Fab Notes:
  drawing of 173 lines, arcs and shapes, not listed
  text "DESIGN INFORMATION" at 8196.12,4203.4 h60
  text "MIN. TRACK WIDTH:" at 7551.56,4023.4 h60
  text "5" at 8647.8,4023.4 h60
  text "MIL" at 8802.56,4023.4 h60
  text "MIN. CLEARANCE:" at 7551.56,3891.4 h60
  text "0.1" at 8587.8,3891.4 h60
  text "mm" at 8802.56,3891.4 h60
  text "MIN. VIA PAD SIZE:" at 7551.56,3759.4 h60
  text "22" at 8617.81,3759.4 h60
  text "MIL" at 8802.56,3759.4 h60
  text "0.05mm (2MIL)" at 8246.56,3617.69 h60
  text "MINIMUM ANNULAR RING" at 7222.33,3613.4 h60
  text "EXTERNAL" at 8954.56,3613.4 h60
  text "PER" at 7422.33,3495.4 h60
  text "IPC-D-275 CLASS 2 LEVEL C" at 7642.33,3495.4 h60
  text "MIL, HOLES" at 9130.56,3383.11 h60
  text "+/-" at 8738.1,3382.4 h60
  text "+/-" at 9592.1,3382.4 h60
  text "REGISTRATION TOLERANCES:" at 7222.33,3377.4 h60
  text "METAL" at 8422.1,3377.4 h60
  text "5" at 8998.3,3377.4 h60
  text "3" at 9831.3,3377.4 h60
  text "MIL" at 9947.56,3377.4 h60
  text "+/-" at 9592.1,3264.4 h60
  text "HOLE SIZE TOLERANCE (UNLESS OTHERWISE SPECIFIED):" at 7222.33,3259.4 h60
  text "3" at 9831.3,3259.4 h60
  text "MIL" at 9947.56,3259.4 h60
  text "MATERIAL:" at 7147.56,3049.94 h60
  text "FR-4 High Tg" at 8134,2909.61 h60
  text "FR-408" at 7568.56,2901.04 h60
  text "OTHER" at 9056.56,2901.04 h60
  text "X" at 7979.1,2897.4 h60
  text "THICKNESS:" at 7222.33,2734.04 h60
  text "X" at 7760.5,2734.04 h60
  text "OTHER" at 9243.6,2734.47 h60
  text "62 MIL (1.6mm) +/- 6MIL" at 7896.21,2732.66 h60
  text "TOLERANCE:" at 7222.33,2576.04 h60
  text "X" at 8061.63,2576.04 h60
  text "ANSI IPC-6012 TYPE 3 CLASS 2" at 8248.58,2576.04 h60
  text "OTHER +/-" at 8248.56,2420.04 h60
  text "BOW & TWIST:" at 7222.33,2263.04 h60
  text "X" at 8061.63,2263.04 h60
  text "ANSI IPC-6012 TYPE 3 CLASS 2" at 8248.58,2263.04 h60
  text "OTHER +/-" at 8248.56,2104.53 h60
  text "DRILLING:" at 7147.56,1966.04 h60
  text "REFERENCE:" at 7222.33,1849.04 h60
  text "X" at 7870.56,1849.04 h60
  text "AS SHOWN" at 8057.56,1849.04 h60
  text "X" at 8771.56,1849.04 h60
  text "NC_DRILL FILES" at 8908.56,1849.04 h60
  text "PTH COPPER THICKNESS:" at 7222.33,1691.04 h60
  text "X" at 8352.56,1691.04 h60
  text "20-30 um" at 8489.56,1691.04 h60
  text "OTHER" at 9206.56,1691.04 h60
  text "BOARD FINISH:" at 7147.56,1532.04 h60
  text "SILKSCREEN:" at 7302.78,1414.04 h60
  text "X" at 8251.56,1414.04 h60
  text "TOP" at 8377.56,1414.04 h60
  text "X" at 8761.56,1414.04 h60
  text "BOTTOM" at 8888.56,1414.04 h60
  text "SILKSCREEN COLOR:" at 7302.78,1247.04 h60
  text "X" at 8250.52,1247.04 h60
  text "WHITE" at 8377.56,1247.04 h60
  text "OTHER" at 8888.56,1247.04 h60
  text "X" at 8381.52,1087.84 h60
  text "GREEN" at 8508.56,1087.84 h60
  text "OTHER" at 9126.56,1087.84 h60
  text "SOLDER RESIST COLOR:" at 7302.78,1077.04 h60
  text "X" at 8381.52,917.84 h60
  text "MATTE" at 8508.56,917.84 h60
  text "SEMI-GLOSS" at 9126.1,917.2 h60
  text "IMMERSION GOLD (ENIG)" at 8208.56,729.32 h60
  text "ENEPIG" at 9546.1,726.04 h60
  text "SURFACE FINISH:" at 7147.56,725.04 h60
  text "X" at 8021.61,725.04 h60
  text "HARD GOLD FINGERS" at 9228,570 h60
  text "IMM. TIN/SILVER OR EQUIV" at 7477.1,568.04 h60
  text "OTHER" at 8908.56,568.04 h60
  text "X" at 8715.61,552.04 h60
  text "ARRAY/PANEL:" at 7147.56,389.04 h60
  text "CUT AND TRIM PER M1 BOARD OUTLINE" at 8208.56,384.75 h60
  text "N.C. ROUTE" at 8208.56,233.04 h60
  text "X" at 8887.56,233.04 h60
  text "V. SCORE" at 9074.56,233.04 h60
  text "CERTIFICATION:" at 7147.56,96.04 h60
  text "MATERIALS AND WORKMANSHIP FOR ALL PCBS" at 7872.56,96.04 h60
  text "TO MEET OR EXCEED THE REQUIREMENTS OF:" at 7872.56,-1.96 h60
  text "X" at 7499.06,-138.47 h60
  text "ANSI IPC-A-600F CLASS ->" at 7638.06,-138.47 h60
  text "X" at 9277.12,-138.47 h60
  text "2" at 9396.06,-138.46 h60
  text "1" at 9081.06,-139.96 h60
  text "3" at 9750.06,-139.96 h60
  text "X" at 8313.12,-297.96 h60
  text "RoHS" at 8450.06,-297.96 h60
  text "OTHER" at 9094.46,-297.96 h60
  text "PER ORDER" at 9491.52,-297.96 h60
  text "ALL BOARDS MUST MEET OR EXCEED UL94-V0 REQUIREMENTS." at 7175.1,-463.6 h60
  text "PCB MUST BEAR THE UL94V-0 UL REGISTERED MATERIAL ID NUMBER" at 7175.1,-583.6 h60
  text "ADDITIONAL REQUIREMENTS:" at 7147.56,-756.96 h60
  text "MICROSECTION:" at 7222.33,-871.96 h60
  text "YES" at 8128.06,-871.96 h60
  text "REQUIRED" at 8989.56,-1028.11 h60
  text "BARE BOARD ELEC. TEST:" at 7222.33,-1030.96 h60
  text "NONE" at 8528.06,-1030.96 h60
  text "X" at 8862.56,-1030.96 h60
  text "PER ORDER" at 9581.56,-1030.96 h60
  text ".Layer_Name" at -3604.9,-2856.09 h60
M11 Gerber Information:
  lines w10: -4473.9,-2927.77 2126.1,-2927.77 ; -4473.9,-2724.43 2128.1,-2724.43 ; -4473.9,-2521.1 -4473.9,-3131.1 -468.9,-3131.1 2128.1,-3131.1 2128.1,-2521.1 -4473.4,-2521.1 -4473.4,-3131.1 -2897.9,-3131.1 ; -2008.9,-3131.1 -2008.9,-2521.1 ; -741.9,-2724.43 -741.9,-2521.1 ; 98.1,-2724.43 98.1,-2521.1 ; 720.1,-3137.6 720.1,-2934.77
  text "ALL ARTWORK VIEWED FROM TOP SIDE" at -4410.4,-2653.27 h60
  text "BOARD #:" at -1933.9,-2653.27 h60
  text ".PRJ_Number" at -1388.4,-2653.27 h60
  text "REV:" at -543.9,-2653.27 h60
  text ".PCB_Rev" at -252.4,-2653.27 h60
  text "SVN REV:" at 294.1,-2653.27 h60
  text ".VersionControl_RevNumber" at 800.1,-2653.27 h60
  text "LAYER NAME =" at -4410.4,-2856.09 h60
  text "TID #:" at -1933.9,-2856.6 h60
  text ".TID" at -1388.4,-2856.6 h60
  text "PLOT NAME =" at -4410.4,-3061.94 h60
  text ".plot_File_Name" at -3604.9,-3061.94 h60
  text "GENERATED    :" at -1931.9,-3061.94 h60
  text ".Print_Date" at -1062.4,-3061.94 h60
  text ".Print_Time" at -333.4,-3061.94 h60
  text "TEXAS INSTRUMENTS" at 931.1,-3061.94 h60
M12 Stackup:
  drawing of 607 lines, arcs and shapes, not listed
  text "Layer" at 2306.38,5808.5 h60
  text "Name" at 2716.29,5808.5 h60
  text "Material" at 3756,5808.5 h60
  text "Thickness" at 4615.77,5808.5 h60
  text "Constant" at 5265.6,5808.5 h60
  text "Board Layer Stack" at 5835.46,5808.5 h60
  text "1" at 2306.38,5688.5 h60
  text "Top Overlay" at 2716.29,5688.5 h60
  text "2" at 2306.38,5568.5 h60
  text "Top Solder" at 2716.29,5568.5 h60
  text "Solder Resist" at 3756,5568.5 h60
  text "0.50mil" at 4615.77,5568.5 h60
  text "3.5" at 5265.6,5568.5 h60
  text "3" at 2306.38,5448.5 h60
  text "Top Layer" at 2716.29,5448.5 h60
  text "Copper" at 3756,5448.5 h60
  text "1.40mil" at 4615.77,5448.5 h60
  text "4" at 2306.38,5328.5 h60
  text "Dielectric1" at 2716.29,5328.5 h60
  text "FR-4" at 3756,5328.5 h60
  text "5.20mil" at 4615.77,5328.5 h60
  text "4.8" at 5265.6,5328.5 h60
  text "5" at 2306.38,5208.5 h60
  text "Internal-Plane 2" at 2716.29,5208.5 h60
  text "Copper" at 3756,5208.5 h60
  text "1.40mil" at 4615.77,5208.5 h60
  text "6" at 2306.38,5088.5 h60
  text "Dielectric6" at 2716.29,5088.5 h60
  text "FR-4" at 3756,5088.5 h60
  text "5.20mil" at 4615.77,5088.5 h60
  text "4.8" at 5265.6,5088.5 h60
  text "7" at 2306.38,4968.5 h60
  text "Mid-Layer 3" at 2716.29,4968.5 h60
  text "Copper" at 3756,4968.5 h60
  text "1.40mil" at 4615.77,4968.5 h60
  text "8" at 2306.38,4848.5 h60
  text "Dielectric2" at 2716.29,4848.5 h60
  text "FR-4" at 3756,4848.5 h60
  text "5.20mil" at 4615.77,4848.5 h60
  text "4.8" at 5265.6,4848.5 h60
  text "9" at 2306.38,4728.5 h60
  text "Mid-Layer 4" at 2716.29,4728.5 h60
  text "Copper" at 3756,4728.5 h60
  text "1.40mil" at 4615.77,4728.5 h60
  text "10" at 2306.38,4608.5 h60
  text "Dielectric3" at 2716.29,4608.5 h60
  text "FR-4" at 3756,4608.5 h60
  text "5.20mil" at 4615.77,4608.5 h60
  text "4.8" at 5265.6,4608.5 h60
  text "11" at 2306.38,4488.5 h60
  text "Internal-Plane 5" at 2716.29,4488.5 h60
  text "Copper" at 3756,4488.5 h60
  text "1.40mil" at 4615.77,4488.5 h60
  text "12" at 2306.38,4368.5 h60
  text "Dielectric8" at 2716.29,4368.5 h60
  text "FR-4" at 3756,4368.5 h60
  text "5.20mil" at 4615.77,4368.5 h60
  text "4.8" at 5265.6,4368.5 h60
  text "13" at 2306.38,4248.5 h60
  text "Internal-Plane 6" at 2716.29,4248.5 h60
  text "Copper" at 3756,4248.5 h60
  text "1.40mil" at 4615.77,4248.5 h60
  text "14" at 2306.38,4128.5 h60
  text "Dielectric7" at 2716.29,4128.5 h60
  text "FR-4" at 3756,4128.5 h60
  text "5.20mil" at 4615.77,4128.5 h60
  text "4.8" at 5265.6,4128.5 h60
  text "15" at 2306.38,4008.5 h60
  text "Mid-Layer 7" at 2716.29,4008.5 h60
  text "Copper" at 3756,4008.5 h60
  text "1.40mil" at 4615.77,4008.5 h60
  text "16" at 2306.38,3888.5 h60
  text "Dielectric5" at 2716.29,3888.5 h60
  text "FR-4" at 3756,3888.5 h60
  text "5.20mil" at 4615.77,3888.5 h60
  text "4.8" at 5265.6,3888.5 h60
  text "17" at 2306.38,3768.5 h60
  text "Mid-Layer 8" at 2716.29,3768.5 h60
  text "Copper" at 3756,3768.5 h60
  text "1.40mil" at 4615.77,3768.5 h60
  text "18" at 2306.38,3648.5 h60
  text "Dielectric4" at 2716.29,3648.5 h60
  text "FR-4" at 3756,3648.5 h60
  text "5.20mil" at 4615.77,3648.5 h60
  text "4.8" at 5265.6,3648.5 h60
  text "19" at 2306.38,3528.5 h60
  text "Internal-Plane 9" at 2716.29,3528.5 h60
  text "Copper" at 3756,3528.5 h60
  text "1.40mil" at 4615.77,3528.5 h60
  text "20" at 2306.38,3408.5 h60
  text "Dielectric9" at 2716.29,3408.5 h60
  text "FR-4" at 3756,3408.5 h60
  text "5.20mil" at 4615.77,3408.5 h60
  text "4.8" at 5265.6,3408.5 h60
  text "21" at 2306.38,3288.5 h60
  text "Bottom Layer" at 2716.29,3288.5 h60
  text "Copper" at 3756,3288.5 h60
  text "1.40mil" at 4615.77,3288.5 h60
  text "22" at 2306.38,3168.5 h60
  text "Bottom Solder" at 2716.29,3168.5 h60
  text "Solder Resist" at 3756,3168.5 h60
  text "0.50mil" at 4615.77,3168.5 h60
  text "3.5" at 5265.6,3168.5 h60
  text "23" at 2306.38,3048.5 h60
  text "Bottom Overlay" at 2716.29,3048.5 h60
  text ".Layer_Name" at -3604.9,-2856.09 h60
M13 Component Bodies Top:
  text ".Layer_Name" at -3604.9,-2856.09 h60
M14 Component Bodies Bottom:
  text ".Layer_Name" at -3604.9,-2856.09 h60
M15 Courtyards Top:
  text ".Layer_Name" at -3604.9,-2856.09 h60
M16 Courtyards Bottom:
  text ".Layer_Name" at -3604.9,-2856.09 h60
Drill Drawing:
  circle w10: c3073.41,2274.33 r33.33
  lines w10: 2362.44,249.21 2362.44,1974.07 -284.6,1974.07 -284.81,1974.27 -284.81,248.62 -93.69,248.62 -93.69,223.46 -93.69,116.22 -93.3,115.84 cw(c-132.26,113.93) -155.78,82.83 -171.91,82.83 -172.17,82.57 -172.17,4.97 2.88,4.97 5.14,2.71 5.14,-231.11 5.27,-230.98 21.09,-230.98 21.21,-230.86 927.59,-230.86 927.34,-230.61 927.34,-34.19 927.3,-34.16 cw(c974.3,-34.16) 1021.3,-34.16 1021.3,-231.15 1021.39,-231.23 2070.29,-231.23 2070.04,-230.98 2070.04,1.83 2073.05,4.84 2247.6,4.84 2247.22,5.22 2247.22,84.2 2246.88,83.86 2231.22,83.86 cw(c2207.7,114.97) 2168.7,114.83 2168.7,245.57 2172.34,249.21 2362.44,249.21 ; 2362.44,249.21 2362.44,249.21 ; 3040.07,2091 3106.74,2091 3106.74,2157.67 3040.07,2157.67 3040.07,2091 ; 3040.07,2391 3073.41,2407.67 3106.74,2391 3090.07,2424.33 3106.74,2457.67 3073.41,2441 3040.07,2457.67 3056.74,2424.33 3040.07,2391 ; 3040.07,2557.67 3056.74,2557.67 3073.41,2541 3090.07,2557.67 3106.74,2557.67 3090.07,2574.33 3106.74,2591 3090.07,2591 3073.41,2607.67 3056.74,2591 3040.07,2591 3056.74,2574.33 3040.07,2557.67
  lines w12: 2980.28,2046 6505.36,2046 ; 2980.28,2646 6505.36,2646 ; 3531.16,1896 3531.16,2796 ; 4121,1896 4121,2796 ; 5220.68,1896 5220.68,2796 ; 5726.56,1896 5726.56,2796 ; 2980.28,1896 6505.36,1896 6505.36,2796 2980.28,2796 2980.28,1896
  text "Symbol" at 3070.28,2691 h72
  text "Count" at 3576.16,2691 h72
  text "Hole Size" at 4166,2691 h72
  text "Plated" at 5265.68,2691 h72
  text "Hole Type" at 5771.56,2691 h72
  text "2" at 3576.16,2541 h60
  text "35.43mil (0.900mm)" at 4166,2541 h60
  text "NPTH" at 5265.68,2541 h60
  text "Round" at 5771.56,2541 h60
  text "8" at 3576.16,2391 h60
  text "35.04mil (0.890mm)" at 4166,2391 h60
  text "PTH" at 5265.68,2391 h60
  text "Round" at 5771.56,2391 h60
  text "9" at 3576.16,2241 h60
  text "25.00mil (0.635mm)" at 4166,2241 h60
  text "PTH" at 5265.68,2241 h60
  text "Round" at 5771.56,2241 h60
  text "493" at 3576.16,2091 h60
  text "8.00mil (0.203mm)" at 4166,2091 h60
  text "PTH" at 5265.68,2091 h60
  text "Round" at 5771.56,2091 h60
  text "512 Total" at 3576.16,1941 h60
  text ".Layer_Name" at -3604.9,-2856.09 h60
M17 Embedded Cavity:
  text ".Layer_Name" at -3604.9,-2856.09 h60
M18 Embedded Assembly:
  text ".Layer_Name" at -3604.9,-2856.09 h60
M19 Embedded Keepout:
  text ".Layer_Name" at -3604.9,-2856.09 h60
